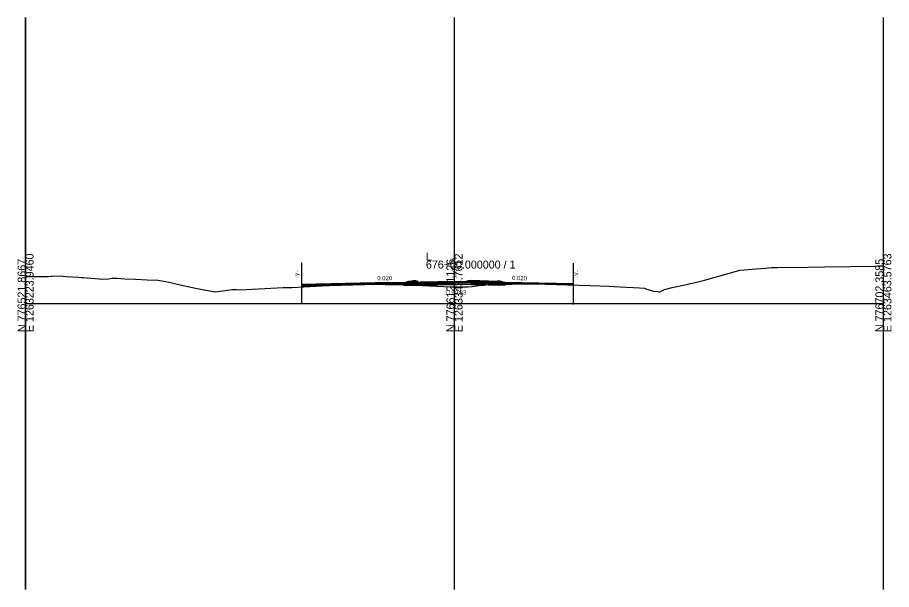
# Model space of a CAD drawing. Extents: x -41 to 1262860, y -100 to 777489.
# Drawn here: x 497.2 to 802.8, y 1390 to 1590 of the extents above; entities that cross this region are included whole.
import ezdxf

# ---------------------------------------------------------------- set-up
doc = ezdxf.new("R2010")
doc.units = 0
for name, color, linetype in [('Exist Cross Section Cell', 7, 'Continuous'), ('Exist XS Center Line Elevation Label', 7, 'Continuous'), ('Exist XS Ground Line', 7, 'Continuous'), ('Prop CMT Pvmt Course 1', 7, 'Continuous'), ('Prop CMT Pvmt Course 4', 7, 'Continuous'), ('Prop CMT Pvmt Surface', 7, 'Continuous'), ('Prop CMT Shear Line', 7, 'Continuous'), ('Prop CMT Shld Paved Course 1', 7, 'Continuous'), ('Prop CMT Shld Paved Course 2', 7, 'Continuous'), ('Prop CMT Shld Paved Course 4', 7, 'Continuous'), ('Prop CMT Subgrade Earthwork', 7, 'Continuous'), ('Prop Conc Curb and Gutter', 7, 'Continuous'), ('Prop Conc Island Cover', 7, 'Continuous'), ('Prop XS Earthwork Shape', 7, 'Continuous'), ('Prop XS Exc Vertical Line 1', 7, 'Continuous'), ('Prop XS Exc Vertical Line 2', 7, 'Continuous'), ('Prop XS Exc Vertical Line 3', 7, 'Continuous'), ('Prop XS Hydro Elevations', 7, 'Continuous'), ('Prop XS SE Text', 7, 'Continuous'), ('Scratch_Level_4', 7, 'Continuous'), ('Scratch_Level_6', 7, 'Continuous')]:
    doc.layers.add(name, color=color, linetype=linetype)

msp = doc.modelspace()

# ---------------------------------------------------------------- linework, layer by layer
at = {"layer": 'Exist Cross Section Cell'}
for p, q in [((650, 1490), (650, 1505)), ((500, 1490), (650, 1490)), ((650, 1490), (800, 1490))]:
    msp.add_line(p, q, dxfattribs=at)
at = {"layer": 'Exist XS Ground Line'}
msp.add_lwpolyline([(500, 1499.4), (500.36, 1499.4), (503.44, 1499.42), (507.48, 1499.44), (507.58, 1499.44), (507.84, 1499.45), (508.94, 1499.52), (509.22, 1499.57), (510.12, 1499.73), (513.08, 1499.53), (514.1, 1499.43), (518.59, 1499.18), (519.27, 1499.11), (520.29, 1499.05), (522.76, 1498.86), (527.16, 1498.51), (529, 1498.68), (530.25, 1498.84), (531.86, 1498.82), (534.75, 1498.61), (538.43, 1498.5), (542.54, 1498.27), (546.26, 1498.21), (549, 1497.64), (551.1, 1497.24), (554, 1496.58), (558.4, 1495.54), (559.96, 1495.23), (563.08, 1494.67), (566.3, 1494.03), (568.03, 1494.37), (572.37, 1494.88), (573.6, 1494.85), (574.92, 1494.77), (579.3, 1495), (590.03, 1495.55), (593.14, 1495.64), (605.86, 1496.27), (606, 1496.28), (606.07, 1496.28), (606.22, 1496.28), (622.81, 1496.74), (631.83, 1496.56), (636.64, 1496.38), (641.23, 1496.16), (643.57, 1496.1), (648.94, 1495.83), (649.26, 1495.83), (649.39, 1495.85), (649.43, 1495.85), (649.61, 1495.85), (651.02, 1495.79), (651.47, 1495.77), (653.74, 1495.78), (654.66, 1495.85), (656.18, 1496), (658.48, 1496.25), (660.24, 1496.43), (661.13, 1496.49), (662.91, 1496.59), (664.14, 1496.66), (664.7, 1496.69), (664.8, 1496.69), (666, 1496.7), (668.74, 1496.73), (677.69, 1496.91), (697.42, 1496.28), (704.1, 1496.07), (704.26, 1496.06), (705.96, 1495.93), (707.98, 1495.8), (714.75, 1495.44), (716.48, 1495.34), (716.96, 1495.18), (719.55, 1494.37), (721.06, 1494.15), (721.72, 1494.02), (722.56, 1494.4), (723.49, 1494.91), (726.11, 1495.54), (727.34, 1495.79), (731.67, 1496.77), (732.56, 1496.94), (733.21, 1497.14), (737.4, 1498.21), (745.31, 1500.41), (749.76, 1501.6), (751.26, 1501.72), (755.55, 1502.1), (758.83, 1502.35), (759.69, 1502.42), (760.84, 1502.53), (763.1, 1502.61), (773.52, 1502.75), (779.5, 1502.77), (797.04, 1503.11), (798.29, 1503.14), (799.16, 1503.13), (800, 1503.13)], dxfattribs=at)
at = {"layer": 'Prop CMT Pvmt Course 1'}
msp.add_line((667.5, 1497.14), (650, 1497.49), dxfattribs=at)
for points in [[(596.5, 1496.67), (596.5, 1496.42), (596.5, 1496.42), (622.15, 1496.94), (622.15, 1496.94), (632.5, 1497.14), (632.5, 1497.39), (632.5, 1497.39), (622.15, 1497.19), (622.15, 1497.19), (596.5, 1496.67), (596.5, 1496.67), (596.5, 1496.67)], [(632.5, 1497.14), (650, 1497.49)], [(691.5, 1496.91), (691.5, 1496.91), (667.59, 1497.39), (667.59, 1497.39), (667.5, 1497.39), (667.5, 1497.39), (667.5, 1497.39), (667.5, 1497.14), (667.5, 1497.14), (667.59, 1497.14), (667.59, 1497.14), (691.5, 1496.66), (691.5, 1496.91)]]:
    msp.add_lwpolyline(points, dxfattribs=at)
at = {"layer": 'Prop CMT Pvmt Course 4'}
for p, q in [((632.5, 1496.35), (632.5, 1496.81)), ((667.5, 1496.35), (650, 1496.7)), ((667.5, 1496.35), (667.5, 1496.81))]:
    msp.add_line(p, q, dxfattribs=at)
msp.add_lwpolyline([(632.5, 1496.35), (650, 1496.7)], dxfattribs=at)
at = {"layer": 'Prop CMT Pvmt Surface'}
msp.add_line((667.5, 1497.39), (650, 1497.74), dxfattribs=at)
for points in [[(596.5, 1496.67), (632.5, 1497.39)], [(632.5, 1497.39), (650, 1497.74)], [(667.5, 1497.39), (691.5, 1496.91)]]:
    msp.add_lwpolyline(points, dxfattribs=at)
at = {"layer": 'Prop CMT Shear Line'}
for p, q in [((596.5, 1504.35), (596.5, 1489.91)), ((691.5, 1504.13), (691.5, 1489.7))]:
    msp.add_line(p, q, dxfattribs=at)
at = {"layer": 'Prop CMT Shld Paved Course 1'}
msp.add_lwpolyline([(650, 1497.74), (650, 1497.74), (638, 1497.5)], dxfattribs=at)
at = {"layer": 'Prop CMT Shld Paved Course 2'}
for p, q in [((605.86, 1496.61), (596.5, 1496.42)), ((596.5, 1496.42), (596.5, 1496.42)), ((596.5, 1496.42), (596.5, 1496.09)), ((596.5, 1496.09), (605.86, 1496.28)), ((596.5, 1496.09), (596.5, 1496.09)), ((606, 1496.61), (605.86, 1496.61)), ((605.86, 1496.61), (605.86, 1496.61)), ((605.86, 1496.28), (605.86, 1496.28)), ((605.86, 1496.28), (606, 1496.28)), ((606.07, 1496.62), (606, 1496.61)), ((606, 1496.28), (606.07, 1496.28)), ((606.22, 1496.62), (606.07, 1496.62)), ((606.07, 1496.28), (606.07, 1496.28)), ((606.07, 1496.28), (606.08, 1496.28)), ((606.08, 1496.28), (606.22, 1496.28)), ((622.15, 1496.94), (606.22, 1496.62)), ((606.22, 1496.62), (606.22, 1496.62)), ((606.22, 1496.62), (606.22, 1496.62)), ((606.22, 1496.62), (606.22, 1496.62)), ((606.22, 1496.28), (606.28, 1496.29)), ((606.28, 1496.29), (622.15, 1496.72)), ((606.28, 1496.29), (606.28, 1496.29)), ((606.28, 1496.29), (606.28, 1496.29)), ((606.28, 1496.29), (606.28, 1496.29)), ((622.81, 1496.95), (622.15, 1496.94)), ((622.15, 1496.72), (622.81, 1496.74)), ((631.83, 1497.13), (622.81, 1496.95)), ((622.81, 1496.95), (622.81, 1496.95)), ((622.81, 1496.95), (622.81, 1496.95)), ((622.81, 1496.74), (622.81, 1496.74)), ((622.81, 1496.74), (622.81, 1496.74)), ((622.81, 1496.74), (625.85, 1496.68)), ((625.85, 1496.68), (631.83, 1496.8)), ((625.85, 1496.68), (625.85, 1496.68)), ((632.5, 1497.14), (631.83, 1497.13)), ((631.83, 1497.13), (631.83, 1497.13)), ((631.83, 1496.8), (632.5, 1496.81)), ((631.83, 1496.8), (631.83, 1496.8)), ((632.5, 1496.81), (632.5, 1497.14)), ((632.5, 1497.14), (632.5, 1497.14)), ((667.5, 1496.81), (650, 1497.16)), ((667.5, 1496.81), (667.5, 1497.14)), ((667.5, 1497.14), (667.5, 1497.14)), ((667.5, 1497.14), (667.5, 1497.14)), ((667.5, 1497.14), (667.59, 1497.14)), ((667.59, 1496.81), (667.5, 1496.81)), ((667.5, 1496.81), (667.5, 1496.81)), ((667.59, 1497.14), (668.74, 1497.12)), ((668.74, 1496.79), (667.59, 1496.81)), ((668.74, 1497.12), (668.74, 1497.12)), ((668.74, 1497.12), (677.69, 1496.94)), ((670.03, 1496.76), (668.74, 1496.79)), ((668.74, 1496.79), (668.74, 1496.79)), ((677.69, 1496.91), (670.03, 1496.76)), ((670.03, 1496.76), (670.03, 1496.76)), ((677.69, 1496.94), (677.69, 1496.94)), ((677.69, 1496.94), (691.5, 1496.66)), ((691.5, 1496.47), (677.69, 1496.91)), ((677.69, 1496.91), (677.69, 1496.91)), ((691.5, 1496.66), (691.5, 1496.66)), ((691.5, 1496.66), (691.5, 1496.66)), ((691.5, 1496.66), (691.5, 1496.47)), ((691.5, 1496.47), (691.5, 1496.47))]:
    msp.add_line(p, q, dxfattribs=at)
msp.add_lwpolyline([(632.5, 1496.81), (650, 1497.16)], dxfattribs=at)
at = {"layer": 'Prop CMT Shld Paved Course 4'}
for p, q in [((605.86, 1496.27), (596.5, 1495.81)), ((606, 1496.28), (605.86, 1496.27)), ((606.07, 1496.28), (606, 1496.28)), ((625.85, 1496.68), (631.83, 1496.56)), ((631.83, 1496.56), (632.5, 1496.54)), ((668.74, 1496.73), (667.5, 1496.72)), ((668.74, 1496.73), (670.03, 1496.76))]:
    msp.add_line(p, q, dxfattribs=at)
at = {"layer": 'Prop CMT Subgrade Earthwork'}
for p, q in [((650, 1496.7), (632.5, 1496.35)), ((632.5, 1496.35), (632.5, 1496.54)), ((667.5, 1496.35), (650, 1496.7)), ((667.5, 1496.72), (667.5, 1496.35))]:
    msp.add_line(p, q, dxfattribs=at)
at = {"layer": 'Prop Conc Curb and Gutter'}
for p, q in [((634.01, 1497.83), (635.01, 1497.85)), ((635.01, 1497.85), (635.01, 1497.41)), ((636.49, 1497.91), (635.49, 1497.93)), ((635.49, 1497.93), (635.49, 1497.49)), ((637.24, 1497.66), (636.49, 1497.91)), ((636.49, 1497.91), (636.49, 1497.91)), ((654.11, 1497.83), (654.86, 1498.08)), ((654.86, 1498.08), (655.86, 1498.1)), ((654.86, 1498.08), (654.86, 1498.08)), ((655.86, 1498.1), (655.86, 1497.66)), ((665.99, 1497.83), (664.99, 1497.85)), ((664.99, 1497.85), (664.99, 1497.41)), ((633.25, 1497.41), (633.26, 1497.58)), ((633.25, 1497.41), (633.25, 1497.41)), ((633.25, 1497.41), (633.25, 1497.28)), ((635.01, 1497.41), (633.25, 1497.41)), ((633.25, 1497.41), (633.25, 1497.41)), ((633.25, 1497.28), (633.25, 1497.28)), ((633.25, 1497.28), (635.01, 1497.28)), ((633.26, 1497.58), (634.01, 1497.83)), ((633.26, 1497.58), (633.26, 1497.58)), ((634.01, 1497.83), (634.01, 1497.83)), ((635.01, 1497.28), (635.01, 1497.41)), ((635.01, 1497.41), (635.01, 1497.41)), ((635.01, 1497.28), (635.01, 1497.28)), ((635.01, 1497.28), (635.01, 1497.28)), ((637.25, 1497.49), (635.49, 1497.49)), ((635.49, 1497.49), (635.49, 1497.36)), ((635.49, 1497.49), (635.49, 1497.49)), ((635.49, 1497.36), (635.49, 1497.36)), ((635.49, 1497.36), (637.25, 1497.36)), ((637.25, 1497.49), (637.24, 1497.66)), ((637.24, 1497.66), (637.24, 1497.66)), ((637.25, 1497.36), (637.25, 1497.49)), ((637.25, 1497.49), (637.25, 1497.49)), ((637.25, 1497.49), (637.25, 1497.49)), ((637.25, 1497.36), (637.25, 1497.36)), ((637.25, 1497.36), (637.25, 1497.36)), ((654.1, 1497.66), (654.11, 1497.83)), ((654.1, 1497.66), (654.1, 1497.66)), ((654.1, 1497.66), (654.1, 1497.54)), ((655.86, 1497.66), (654.1, 1497.66)), ((654.1, 1497.66), (654.1, 1497.66)), ((654.1, 1497.54), (654.1, 1497.54)), ((654.1, 1497.54), (655.86, 1497.54)), ((654.11, 1497.83), (654.11, 1497.83)), ((655.86, 1497.54), (655.86, 1497.66)), ((655.86, 1497.66), (655.86, 1497.66)), ((655.86, 1497.54), (655.86, 1497.54)), ((655.86, 1497.54), (655.86, 1497.54)), ((666.75, 1497.41), (664.99, 1497.41)), ((664.99, 1497.41), (664.99, 1497.28)), ((664.99, 1497.41), (664.99, 1497.41)), ((664.99, 1497.28), (664.99, 1497.28)), ((664.99, 1497.28), (666.75, 1497.28)), ((666.74, 1497.58), (665.99, 1497.83)), ((665.99, 1497.83), (665.99, 1497.83)), ((666.75, 1497.41), (666.74, 1497.58)), ((666.74, 1497.58), (666.74, 1497.58)), ((666.75, 1497.28), (666.75, 1497.41)), ((666.75, 1497.41), (666.75, 1497.41)), ((666.75, 1497.41), (666.75, 1497.41)), ((666.75, 1497.28), (666.75, 1497.28)), ((666.75, 1497.28), (666.75, 1497.28))]:
    msp.add_line(p, q, dxfattribs=at)
at = {"layer": 'Prop Conc Island Cover'}
for p, q in [((635.49, 1497.93), (635.01, 1497.85)), ((635.01, 1497.85), (635.01, 1497.6)), ((635.49, 1497.68), (635.49, 1497.93)), ((635.49, 1497.93), (635.49, 1497.93)), ((655.86, 1498.1), (655.86, 1497.85)), ((655.86, 1498.1), (664.99, 1497.85)), ((655.86, 1497.85), (664.99, 1497.6)), ((664.99, 1497.6), (664.99, 1497.85)), ((664.99, 1497.85), (664.99, 1497.85)), ((635.49, 1497.67), (635.01, 1497.59)), ((635.49, 1497.68), (635.49, 1497.68)), ((664.99, 1497.6), (664.99, 1497.6))]:
    msp.add_line(p, q, dxfattribs=at)
at = {"layer": 'Prop XS Earthwork Shape'}
for points in [[(632.5, 1496.54), (635.74, 1496.42), (632.5, 1496.35)], [(650, 1496.7), (635.74, 1496.42), (636.64, 1496.38), (641.23, 1496.16), (643.57, 1496.1), (648.94, 1495.83), (649.26, 1495.83), (649.39, 1495.85), (649.43, 1495.85), (649.61, 1495.85), (651.02, 1495.79), (651.47, 1495.77), (653.74, 1495.78), (654.66, 1495.85), (656.18, 1496), (658.48, 1496.25), (660.24, 1496.43), (661.04, 1496.48)], [(661.13, 1496.49), (662.91, 1496.59), (664.14, 1496.66), (664.7, 1496.69), (664.8, 1496.69), (666, 1496.7), (667.5, 1496.72), (667.5, 1496.35), (661.04, 1496.48)]]:
    msp.add_lwpolyline(points, close=True, dxfattribs=at)
at = {"layer": 'Prop XS Exc Vertical Line 1'}
msp.add_line((500, 1390), (500, 1590), dxfattribs=at)
at = {"layer": 'Prop XS Exc Vertical Line 2'}
msp.add_line((650, 1390), (650, 1590), dxfattribs=at)
at = {"layer": 'Prop XS Exc Vertical Line 3'}
msp.add_line((800, 1390), (800, 1590), dxfattribs=at)
at = {"layer": 'Scratch_Level_4'}
msp.add_line((800, 1390), (800, 1590), dxfattribs=at)
at = {"layer": 'Scratch_Level_6'}
msp.add_line((500, 1590), (500, 1390), dxfattribs=at)

# ---------------------------------------------------------------- texts
at = {"layer": 'Exist Cross Section Cell'}
for s, p in [('E 1263223.9460', (502.8, 1480)), ('E 1263343.7612', (652.8, 1480)), ('E 1263463.5763', (802.8, 1480)), ('N 776521.8667', (500, 1480)), ('N 776612.1126', (650, 1480)), ('N 776702.3585', (800, 1480))]:
    msp.add_text(s, height=2.8, rotation=90, dxfattribs=at).set_placement(p)
for s, p in [('L', (640, 1505)), ('676+00.000000 / 1', (640, 1502.2))]:
    msp.add_text(s, height=2.8, dxfattribs=at).set_placement(p)
at = {"layer": 'Exist XS Center Line Elevation Label'}
msp.add_text('1190.83', height=1.5, dxfattribs=at).set_placement((646.58, 1493.08))
at = {"layer": 'Prop XS Hydro Elevations'}
for s, p in [('1192.74', (650.75, 1498.73)), ('-Y-', (595.81, 1498.81)), ('-Y-', (693.46, 1498.9))]:
    msp.add_text(s, height=1.5, rotation=90, dxfattribs=at).set_placement(p)
at = {"layer": 'Prop XS SE Text'}
for rotation, p in [(1.1458, (623.01, 1498.07)), (358.8542, (670.13, 1498.19))]:
    msp.add_text('0.020', height=1.5, rotation=rotation, dxfattribs=at).set_placement(p)

doc.saveas('drawing.dxf')
